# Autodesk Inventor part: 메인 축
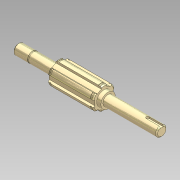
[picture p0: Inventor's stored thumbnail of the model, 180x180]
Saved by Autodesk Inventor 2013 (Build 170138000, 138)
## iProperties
Company: 한국ATC센터
Created: 2014-07
Part Number: 메인 축
Document SubType Name: 모델링
Designer: KYOUNG IL JANG
Mass: 12.2243 g
Surface Area: 72.5108 cm^2
Volume: 21.4461 cm^3
Density: 0.57 g/cm^3
Material: 강철, 연강
변환 표준: STEP AP214IS
파일 이름: C:\Users\SeoGD\Desktop\?쒗뿕\硫붿씤 異?.stp
전처리기: Build: 253, Release: 2010 SP1 - Date: Wed 07/29/2009
전송 단위: 밀리미터
불확실성: 0.01
Author: KYOUNG IL JANG
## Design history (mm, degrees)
sketch "스케치1"
  geometry: L1 (-69.5, 0)-(69.5, 0); L2 (69.5, 0)-(69.5, 5); L3 (69.5, 5)-(55.5, 5); L4 (55.5, 5)-(55.5, 4.8); L5 (55.5, 4.8)-(54.35, 4.8); L6 (54.35, 4.8)-(54.35, 5); L7 (54.35, 5)-(30.5, 5); L8 (30.5, 5)-(30.5, 9); L9 (30.5, 9)-(-13.5, 9); L10 (-13.5, 9)-(-13.5, 7); L11 (-13.5, 7)-(-17.5, 7); L12 (-17.5, 7)-(-17.5, 5); L13 (-17.5, 5)-(-69.5, 5); L14 (-69.5, 5)-(-69.5, 0); 2 further points
  constraints: 28 end point, 9 parallel, 4 collinear, 2 perpendicular, 1 coincident, 1 horizontal, 1 midpoint
  dimensions: "d2" = 1.15 distance between parallel lines of L6 L4; "d3" = 10 diameter of L3 L1; "d4" = 9.6 diameter of L5 L1; "d6" = 44 distance between parallel lines of L10 L8; "d7" = 4 distance between parallel lines of L12 L10; "d8" = 14 diameter of L11 L1; "d9" = 18 diameter of L9 L1; "d33" = 52 distance from line of L12.end L14; "d37" = 39 distance between parallel lines of L8 L2; "d38" = 14 distance between parallel lines of L2 L4
revolve "회전1" sketch "스케치1" stored, may be unused: angle "d10" = 90 deg
sketch "스케치2"
  geometry: L1 (2.5, 10.712)-(2.5, 8.646); L2 (-2.5, 10.712)-(-2.5, 8.646); A1 r 9 centre (0, 0) between (2.5, 8.646) and (-2.5, 8.646) reference; A2 r 11 centre (0, 0) between (2.5, 10.712) and (-2.5, 10.712); 1 further point
  constraints: 4 end point, 4 point on circle, 2 parallel, 1 centre point, 1 coincident, 1 vertical
  dimensions: "d11" = 22 diameter of A2; "d12" = 5 distance between parallel lines of L1 L2
extrude "돌출1" join sketch "스케치2" stored distance "d13" = 10; taper "d14" = 0 deg
chamfer "모따기1" distance "d15" = 1; stored, may be unused: second distance "d16" = 2, angle "d17" = 45 deg
node "작업 평면1"
node "작업 평면2"
sketch "스케치3"
  geometry: L1 (2.5, 10.712)-(2.5, 10.198); L2 (-2.5, 10.712)-(-2.5, 10.198); A1 r 11 centre (0, 0) between (2.5, 10.712) and (-2.5, 10.712) reference; A2 r 10.5 centre (0, 0) between (2.5, 10.198) and (-2.5, 10.198); 1 further point
  constraints: 4 end point, 2 point on circle, 1 centre point, 1 coincident, 1 parallel, 1 vertical
  dimensions: "d19" = 21 diameter of A2
extrude "돌출2" cut sketch "스케치3" distance "d20" = 1.35; taper "d21" = 0 deg
node "작업 평면3"
sketch "스케치4"
  geometry: L1 (-26, -5)-(-26, 5) reference; L2 (-26, 1.5)-(-12.5, 1.5); L3 (-12.5, -1.5)-(-26, -1.5); A1 r 1.5 centre (-12.5, 0) between (-12.5, -1.5) and (-12.5, 1.5); 2 further points
  constraints: 4 end point, 2 perpendicular, 2 point on circle, 2 point on line, 2 tangent, 1 centre point, 1 horizontal alignment, 1 midpoint
  dimensions: "d25" = 3 distance between parallel lines of L3 L2; "d26" = 15 dimension on A1 L1
extrude "돌출3" cut sketch "스케치4" distance "d27" = 1.8; taper "d28" = 0 deg
chamfer "모따기2" distance "d29" = 1; stored, may be unused: second distance "d30" = 2, angle "d31" = 45 deg
node "솔리드1"
node "솔리드 본체"
node "곡면 본체"
mirror "대칭1"
pattern_circular "원형 패턴1" dims "d23" = 360 deg
node "솔리드2"
other parameters: "d18" = -1.65
